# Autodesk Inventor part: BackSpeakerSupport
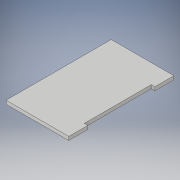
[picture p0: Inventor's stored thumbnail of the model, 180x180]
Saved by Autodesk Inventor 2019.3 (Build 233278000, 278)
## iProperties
Created: 2020-02
Part Number: BackSpeakerSupport
Material: Generic
Document SubType Name: Modeling
Designer: KrystynWikoff
Density: 1 g/cm^3
Appearance: Default
Author: KrystynWikoff
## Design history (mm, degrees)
sketch "Sketch1"
  geometry: L1 (0, 0)-(41.732, 0); L2 (41.732, 0)-(41.732, -70); L3 (41.732, -70)-(0, -70); L4 (0, -70)-(0, 0)
  constraints: 8 end point, 2 parallel, 1 horizontal, 1 perpendicular
  dimensions: "d0" = 70 distance of L3.end L1.start; "d1" = 41.7322 distance of L1.start L1.end
extrude "Extrusion1" new body sketch "Sketch1" distance "d2" = 2.3622; taper "d3" = 0 deg
sketch "Sketch3"
  geometry: L1 (0, 0)-(0, 70) reference; L2 (0, 12.7)-(-2.362, 12.7); L3 (-2.362, 12.7)-(-2.362, 57.3); L4 (-2.362, 57.3)-(0, 57.3); L5 (0, 57.3)-(0, 12.7); L6 (-41.732, 0)-(0, 0) reference; L7 (0, 70)-(-41.732, 70) reference
  constraints: 8 end point, 2 parallel, 1 horizontal, 1 perpendicular, 1 point on line
  dimensions: "d11" = 12.7 distance between parallel lines of L6 L2; "d12" = 12.7 distance between parallel lines of L7 L4; "d13" = 2.3622 distance of L2.start L2.end
extrude "Extrusion3" cut sketch "Sketch3" distance "d14" = 25.4; taper "d15" = 0 deg
body "Solid1"
